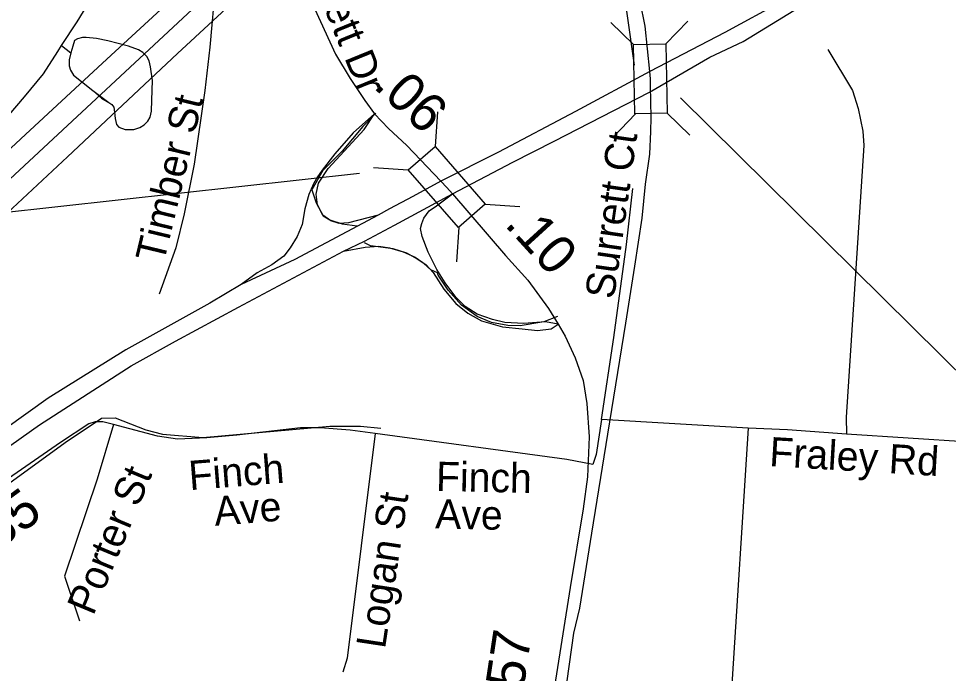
# Model space of a CAD drawing. Extents: x 1662474 to 1856135, y 779280 to 917889.
# Drawn here: x 1702130 to 1705150, y 793367 to 795494 of the extents above; entities that cross this region are included whole.
import ezdxf

# ---------------------------------------------------------------- set-up
doc = ezdxf.new("R2010")
doc.units = 0
for name, color, linetype in [('Exist Hydrographic Misc Water Feature', 7, 'Continuous'), ('Exist Railroad Mainline', 7, 'Continuous'), ('Exist Railroad Structure Bridge CELL', 7, 'Continuous'), ('Exist Railroad Structure Bridge Number Label', 7, 'Continuous'), ('Exist Road Non-System Type 51', 7, 'Continuous'), ('Exist Road Non-System Type 51 Label', 7, 'Continuous'), ('Exist Road Primary Interstate Divided Center Attributed', 7, 'Continuous'), ('Exist Road Primary Interstate Ramp 1 Lane Attributed', 7, 'Continuous'), ('Exist Road Primary Interstate Service Attributed', 7, 'Continuous'), ('Exist Road Primary Interstate Service Mileage Tenths English Label', 7, 'Continuous'), ('Exist Road Secondary Mileage Hundredths English Label', 7, 'Continuous'), ('Exist Road Secondary Structure Standard Bridge CELL', 7, 'Continuous'), ('Exist Road Secondary Structure Standard Bridge Number Label', 7, 'Continuous'), ('Exist Road Secondary Type 51 Attributed', 7, 'Continuous'), ('Exist Road Secondary Type 51 Label', 7, 'Continuous'), ('Exist Utilities Electrical Transmission Line', 7, 'Continuous')]:
    doc.layers.add(name, color=color, linetype=linetype)

msp = doc.modelspace()

# ---------------------------------------------------------------- linework, layer by layer
at = {"layer": 'Exist Hydrographic Misc Water Feature'}
msp.add_line((1702270.2, 795406.7), (1702300.1, 795383.1), dxfattribs=at)
for points in [[(1702270.2, 795406.7), (1702320.3, 795483.6), (1702376.4, 795576.9), (1702461.1, 795754.8), (1702577.7, 795960.1), (1702635.9, 796030.3), (1702672.2, 796054.2), (1702708.2, 796079.7), (1702734.4, 796107.9), (1702756.3, 796140.3), (1702782.7, 796231.6), (1702806.9, 796265.6), (1702849, 796297.6), (1702903, 796317), (1702987, 796343.2), (1703051.1, 796345.2), (1703096.1, 796339.3)], [(1702300.1, 795383.1), (1702294.1, 795360.2), (1702294.6, 795340.5), (1702298.8, 795326.5), (1702308.7, 795310.8), (1702371.1, 795261.1), (1702399.6, 795235.9), (1702423.7, 795222.2), (1702433.2, 795215.5), (1702439.7, 795206.3), (1702441.8, 795189.9), (1702444.1, 795170.1), (1702448.2, 795150.3), (1702456.3, 795142), (1702476.5, 795134.2), (1702504.6, 795134.4), (1702523.7, 795140.6), (1702538.3, 795149.3), (1702550.2, 795160.6), (1702558.1, 795173.6), (1702561.9, 795193.2), (1702563.4, 795229.2), (1702565, 795293.2), (1702558.6, 795337.6), (1702553.9, 795356.6), (1702546.3, 795371.6), (1702533.8, 795384.1), (1702520.1, 795392.6), (1702487.8, 795404.8), (1702419.7, 795421.7), (1702383.6, 795429.8), (1702349.6, 795433), (1702337.7, 795433.3), (1702321.6, 795428.6), (1702311.5, 795423.1), (1702306, 795404.3), (1702300.1, 795383.1)], [(1702300.1, 795383.1), (1702294.1, 795360.2), (1702294.6, 795340.5), (1702298.8, 795326.5), (1702308.7, 795310.8), (1702371.1, 795261.1), (1702423.7, 795222.2), (1702433.2, 795215.5), (1702439.7, 795206.3), (1702441.8, 795189.9), (1702444.1, 795170.1), (1702448.2, 795150.3), (1702456.3, 795142), (1702476.5, 795134.2), (1702504.6, 795134.4), (1702523.7, 795140.6), (1702538.3, 795149.3), (1702550.2, 795160.6), (1702558.1, 795173.6), (1702561.9, 795193.2), (1702563.4, 795229.2), (1702565, 795293.2), (1702558.6, 795337.6), (1702553.9, 795356.6), (1702546.3, 795371.6), (1702533.8, 795384.1), (1702520.1, 795392.6), (1702487.8, 795404.8), (1702419.7, 795421.7), (1702383.6, 795429.8), (1702349.6, 795433), (1702337.7, 795433.3), (1702321.6, 795428.6), (1702311.5, 795423.1), (1702306, 795404.3), (1702300.1, 795383.1)], [(1702054.9, 795130.4), (1702149.5, 795240.1), (1702211.8, 795315.1), (1702257.9, 795387.2), (1702270.2, 795406.7)]]:
    msp.add_lwpolyline(points, dxfattribs=at)
at = {"layer": 'Exist Railroad Mainline'}
msp.add_lwpolyline([(1703904.2, 793289.3), (1703933.5, 793498.1), (1703953, 793579.2), (1703992, 793822.8), (1704044, 794144.2), (1704102.5, 794504.7), (1704131.8, 794689.8), (1704155.1, 794846.5), (1704166.2, 794956.9), (1704179.9, 795053.9), (1704182.8, 795127.9), (1704184.7, 795172.8), (1704182.1, 795277.3), (1704181.9, 795298.4), (1704180.2, 795322.6), (1704165.4, 795469.5), (1704148.6, 795550.1)], dxfattribs=at)
at = {"layer": 'Exist Railroad Structure Bridge CELL'}
for p, q in [((1704303.8, 795486.2), (1704232.4, 795412)), ((1704053, 795481.4), (1704127.1, 795410.1)), ((1704133.3, 795184.8), (1704061.9, 795110.7)), ((1704236.2, 795186.7), (1704310.3, 795115.4))]:
    msp.add_line(p, q, dxfattribs=at)
msp.add_lwpolyline([(1704232.4, 795412), (1704236.7, 795186.7), (1704131.4, 795184.7), (1704127.1, 795410.1)], close=True, dxfattribs=at)
at = {"layer": 'Exist Railroad Structure Bridge Number Label'}
msp.add_line((1704279.7, 795236.4), (1706118.7, 793417.4), dxfattribs=at)
at = {"layer": 'Exist Road Non-System Type 51'}
for p, q in [((1704499.9, 794164.1), (1704022.8, 794192.2)), ((1704499.9, 794164.1), (1704380.8, 792298.8)), ((1705436.1, 794104), (1704818.8, 794144.9))]:
    msp.add_line(p, q, dxfattribs=at)
for points in [[(1703872.9, 796759.1), (1703933, 796507.1), (1703991.8, 796195.4), (1704019.9, 796018.9), (1704080.1, 795686.9), (1704129.2, 795343.4)], [(1702941.4, 795905.2), (1702927.5, 795907.4), (1702910.6, 795898.2), (1702809.9, 795779.9), (1702793.4, 795747.9), (1702785.8, 795725.5), (1702770, 795608.4), (1702751.9, 795401.9), (1702735.1, 795260.2), (1702700.1, 795021.6), (1702668.1, 794859.9), (1702640.9, 794749.2), (1702586.9, 794598.8)], [(1704758.4, 795393.8), (1704837.9, 795260.2), (1704856.9, 795202.7), (1704871.5, 795128.9), (1704874.6, 795081.9), (1704817.1, 794199.5), (1704818.8, 794144.9)], [(1703289.9, 795187.4), (1703248.5, 795143.9), (1703181.2, 795064.1), (1703118, 795000.9), (1703082.6, 794937.9), (1703097, 794896.1), (1703119.4, 794853.6), (1703141.4, 794840.8), (1703181, 794827.9), (1703229.4, 794821.4)], [(1704022.8, 794192.2), (1704063.1, 794458.4), (1704104.1, 794760.7), (1704124.6, 794942.9)], [(1703880.5, 794526.6), (1703835.4, 794509.8), (1703759.2, 794496.1), (1703719.1, 794497.7), (1703666.4, 794507.7), (1703619.9, 794526.4), (1703568.1, 794563.1), (1703525.6, 794612.1), (1703492.9, 794660.9), (1703491, 794668.2), (1703468.9, 794678.5), (1703446.4, 794699), (1703418.5, 794717.7), (1703391, 794732.6), (1703346.9, 794746.5), (1703273.1, 794755.7), (1703253.8, 794766.4)], [(1702439, 794176.2), (1702404.1, 794184.1), (1702379.4, 794185.1), (1702358.1, 794177.8), (1702266.6, 794117.4), (1702097.9, 794000.6), (1701414.6, 793494.9), (1701392.4, 793472.2), (1701389.1, 793464.1), (1701378.6, 793435.8), (1701378.6, 793372.5), (1701392.6, 792827.1)], [(1704022.8, 794192.2), (1704005.6, 794078.9), (1703995.1, 794045.8)], [(1702439, 794176.2), (1702385.2, 793998.8), (1702279.8, 793683), (1702327.8, 793538.4)], [(1703287.9, 794146.5), (1703207.5, 794157.5), (1703109.6, 794164.9), (1703045.4, 794165.2), (1702839.2, 794141), (1702741.1, 794132.4), (1702646.1, 794128.4), (1702581.2, 794137.6), (1702439, 794176.2)], [(1704818.8, 794144.9), (1704627.4, 794158.4), (1704499.9, 794164.1)], [(1703287.9, 794146.5), (1703197, 793416.6), (1703183.1, 793371.5)], [(1703995.1, 794045.8), (1703910.1, 794062.5), (1703287.9, 794146.5)]]:
    msp.add_lwpolyline(points, dxfattribs=at)
at = {"layer": 'Exist Road Primary Interstate Divided Center Attributed'}
for points in [[(1705590.5, 796146.6), (1705375.7, 796016.4), (1705051.1, 795807.8), (1704798.5, 795654.1), (1704424, 795449.2), (1704180.2, 795322.6)], [(1704178.7, 795254.8), (1704374.6, 795369.5), (1704483.3, 795420.2), (1704812.7, 795622.8), (1705087.3, 795781.1), (1705354.6, 795961.9), (1705527.4, 796074.5)], [(1704180.2, 795322.6), (1703938.6, 795192.5), (1703688.2, 795060.2), (1703501, 794966)], [(1703539.4, 794925.5), (1703735.3, 795028.2), (1703869.9, 795095.8), (1704178.7, 795254.8)], [(1703501, 794966), (1703410.8, 794916.1), (1703335.2, 794876.5), (1703298.2, 794855.3)], [(1703184.9, 794739), (1703253.7, 794771.5), (1703351, 794823.7), (1703539.4, 794925.5)], [(1703298.2, 794855.3), (1703027.8, 794712), (1702853.3, 794630.4)], [(1700381.7, 792830.1), (1700522.6, 792935.7), (1700907.4, 793226.8), (1701330.4, 793540.5), (1701557.2, 793709.6), (1701883.2, 793948.4), (1702037, 794061.4), (1702197.8, 794175), (1702495.5, 794366.2), (1702639.7, 794446.7), (1702844.8, 794557.1), (1703184.9, 794739)], [(1702853.3, 794630.4), (1702750.9, 794569.7), (1702479, 794418), (1702226.1, 794261.6), (1702015.2, 794111.1), (1701830, 793976.6), (1701479.5, 793719.9), (1701237.6, 793540), (1700863.6, 793263), (1700730.9, 793171.6), (1700489.1, 792985.6), (1700346.4, 792876.8)]]:
    msp.add_lwpolyline(points, dxfattribs=at)
at = {"layer": 'Exist Road Primary Interstate Ramp 1 Lane Attributed'}
for points in [[(1703285.9, 795185.4), (1703217, 795123.6), (1703157.1, 795054.8), (1703116.5, 795001.8), (1703100.6, 794980.7), (1703088.3, 794957.7), (1703072.4, 794922.4), (1703060, 794876.5), (1703051.2, 794825.3), (1703035.3, 794786.5), (1703012.4, 794749.4), (1702991.2, 794722.9), (1702952.4, 794694.7), (1702904.8, 794668.2), (1702853.3, 794630.4)], [(1703298.2, 794855.3), (1703201.2, 794830.6), (1703171.2, 794828.8), (1703144.7, 794837.7), (1703118.3, 794855.3), (1703100.6, 794888.9), (1703097.1, 794924.2), (1703104.1, 794959.5), (1703135.9, 795007.1), (1703252.3, 795134.2), (1703285.9, 795185.4)], [(1703550.6, 794590), (1703515.2, 794636.4), (1703488.7, 794678.8), (1703460.5, 794735.3), (1703441.1, 794786.5), (1703435.8, 794813), (1703439.3, 794828.8), (1703446.4, 794846.5), (1703463.1, 794869.9), (1703487.6, 794886.4), (1703539.4, 794925.5)], [(1703184.9, 794739), (1703256.1, 794751.7), (1703299.9, 794755.4), (1703335.2, 794749.4), (1703379.4, 794737.1), (1703418.2, 794719.4), (1703453.4, 794694.7), (1703476.4, 794670), (1703511.7, 794615.3), (1703550.5, 794569.4), (1703589.3, 794537.6), (1703633.4, 794512.9), (1703702.2, 794493.5), (1703765.7, 794486.4), (1703815.1, 794481.1), (1703859.2, 794486.4), (1703869.8, 794493.5), (1703882.1, 794502.3)], [(1703882.1, 794502.3), (1703841.6, 794509.3), (1703771, 794504.1), (1703709.3, 794507.6), (1703668.7, 794516.4), (1703619.3, 794534.1), (1703580.5, 794558.8), (1703550.6, 794590)]]:
    msp.add_lwpolyline(points, dxfattribs=at)
at = {"layer": 'Exist Road Primary Interstate Service Attributed'}
msp.add_lwpolyline([(1701393.8, 792831.7), (1701386.5, 792932.5), (1701366.2, 793307.1), (1701366.7, 793429.2), (1701377.1, 793455), (1701426.8, 793498), (1702061.5, 793958.6), (1702282.1, 794117.7), (1702399.3, 794196.2), (1702444.2, 794197.8), (1702543.9, 794158.6), (1702597.5, 794144.8), (1702728.1, 794133.4), (1703140.9, 794170.4), (1703241, 794170.3), (1703306.2, 794164)], dxfattribs=at)
at = {"layer": 'Exist Road Secondary Structure Standard Bridge CELL'}
for p, q in [((1703491, 795191.6), (1703483.2, 795078.7)), ((1703282.9, 795010.5), (1703395.8, 795002.7)), ((1703645.5, 794891.3), (1703758.4, 794883.5)), ((1703560.1, 794817), (1703552.2, 794704.1))]:
    msp.add_line(p, q, dxfattribs=at)
msp.add_lwpolyline([(1703483.2, 795078.7), (1703645.9, 794891.7), (1703558.5, 794815.7), (1703395.8, 795002.7)], close=True, dxfattribs=at)
at = {"layer": 'Exist Road Secondary Structure Standard Bridge Number Label'}
msp.add_line((1703237.3, 794990.8), (1701205.9, 794766.6), dxfattribs=at)
at = {"layer": 'Exist Road Secondary Type 51 Attributed'}
for points in [[(1702565.1, 796765.7), (1702637.3, 796620.6), (1702717.9, 796438), (1702812.1, 796201.2), (1702957.8, 795849.6), (1703031.1, 795662.6), (1703092, 795525.3), (1703159.4, 795378.8), (1703206.9, 795299.6), (1703254.5, 795228.4), (1703285.9, 795185.4)], [(1703501, 794966), (1703391.2, 795082.3), (1703332, 795137.4), (1703285.9, 795185.4)], [(1703539.4, 794925.5), (1703520.8, 794945.3), (1703501, 794966)], [(1703539.4, 794925.5), (1703711.1, 794725), (1703784.4, 794644.7), (1703850.6, 794552.6), (1703882.1, 794502.3)], [(1703882.1, 794502.3), (1703904.9, 794462.9), (1703938, 794392.1), (1703964, 794318.9), (1703975.8, 794244.3), (1703982.9, 794135.7), (1703978.2, 794005.9), (1703964, 793902), (1703921.5, 793646.3), (1703829.4, 793065.1), (1703801.1, 792876.3), (1703775.1, 792692.1), (1703763.3, 792569.4), (1703765.8, 792455.1), (1703783.3, 792244.4), (1703810.3, 791999.9), (1703846.8, 791709.2), (1703864.7, 791544.9)]]:
    msp.add_lwpolyline(points, dxfattribs=at)
at = {"layer": 'Exist Utilities Electrical Transmission Line'}
for points in [[(1704137.3, 796780.5), (1703839.6, 796606.2), (1703655.1, 796491.1), (1703482.1, 796342.3), (1703035.9, 795932.6), (1702754.3, 795674.4), (1702416.4, 795362.5), (1702152.8, 795117.8), (1701885.5, 794869.5), (1701619.8, 794622.8), (1701475.4, 794491.8), (1701332.6, 794362.4), (1701251, 794418.9), (1701185.6, 794575.5), (1701126.7, 794746)], [(1704176.7, 796741.9), (1703861.4, 796548), (1703690.7, 796431), (1703099.6, 795902.8), (1701742.3, 794638.8), (1701249.7, 794222.9), (1701018.9, 794076.3), (1700799.5, 793859.5), (1700485.9, 793563.3), (1700145.8, 793239.3), (1699828.1, 792932.9), (1699560.7, 792676.4), (1699238.8, 792376.4), (1698967.3, 792115.7), (1698848.5, 792002.6), (1698780.1, 791948.8), (1698452.8, 791705), (1698238, 791554.1), (1697906.8, 791173.4)], [(1704303, 796746.1), (1703891.2, 796491.9), (1703732.7, 796382.9), (1703603.9, 796265.3), (1703350.3, 796026.9), (1703004.5, 795712.9), (1702646.5, 795380.8), (1702288.8, 795045.1), (1701898.4, 794681.1), (1701550.5, 794361.3), (1701329.2, 794162.6), (1701070.3, 794003.7), (1700847.2, 793799.2), (1700523.3, 793495.2), (1700131.3, 793123.4), (1699807.4, 792819.1), (1699461.3, 792489.1), (1699192.1, 792226.7), (1698964.9, 792011.7), (1698837.9, 791900.7), (1698506.5, 791650.4), (1698309.9, 791503.8), (1698006.2, 791167.8)]]:
    msp.add_lwpolyline(points, dxfattribs=at)

# ---------------------------------------------------------------- texts
at = {"layer": 'Exist Road Non-System Type 51 Label'}
for s, rotation, p in [('Surrett Dr', 292.197, (1703029.7, 795753.6)), ('Timber St', 76.5227, (1702601.6, 794697.1)), ('Surrett Ct', 81.9499, (1704063.5, 794580.5)), ('Fraley Rd', 356.6264, (1704566.4, 794040.8)), ('Porter St', 67.4335, (1702372.8, 793552.2)), ('Finch ', 358.7559, (1703485.1, 793960.3)), ('Logan St', 81.3772, (1703320, 793445)), ('Ave', 358.7559, (1703482.4, 793838.4))]:
    msp.add_text(s, height=95, rotation=rotation, dxfattribs=at).set_placement(p)
at = {"layer": 'Exist Road Primary Interstate Service Mileage Tenths English Label'}
msp.add_text('.35', height=125, rotation=36.2498, dxfattribs=at).set_placement((1702026.2, 793739.2))
at = {"layer": 'Exist Road Secondary Mileage Hundredths English Label'}
for s, rotation, p in [('.06', 317.1376, (1703278.9, 795271.9)), ('.10', 312.3883, (1703705.5, 794823.8)), ('.57', 81.4601, (1703762.6, 793267.8))]:
    msp.add_text(s, height=125, rotation=rotation, dxfattribs=at).set_placement(p)
at = {"layer": 'Exist Road Secondary Type 51 Label'}
for s, p in [('Finch ', (1702686.3, 793962.5)), ('Ave', (1702768.5, 793846.6))]:
    msp.add_text(s, height=95, rotation=4.523, dxfattribs=at).set_placement(p)

doc.saveas('drawing.dxf')
